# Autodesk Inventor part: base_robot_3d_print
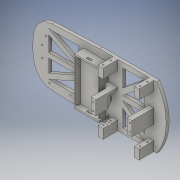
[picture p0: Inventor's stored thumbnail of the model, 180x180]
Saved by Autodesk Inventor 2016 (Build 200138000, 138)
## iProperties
Created: 2016-07
Part Number: base_robot_3d_print
Material: Generic
Document SubType Name: Modeling
Designer: jose
Density: 1 g/cm^3
Appearance: Default
Author: jose
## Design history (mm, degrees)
sketch "Sketch1"
  geometry: C1 r 88.9 at (0, 0); 1 further point
  constraints: 1 centre point, 1 coincident
  dimensions: "d0" = 177.8 diameter of C1
extrude "Extrusion1" new body sketch "Sketch1" distance "d1" = 4.0894; taper "d2" = 0 deg
sketch "Sketch2"
  geometry: L1 (0, 88.9)-(76.2, 88.9); L2 (76.2, 88.9)-(76.2, -88.9); L3 (76.2, -88.9)-(0, -88.9); L4 (0, -88.9)-(0, 88.9); C1 r 88.9 at (0, 0) reference; A1 r 88.9 centre (0, 0) between (0, -88.9) and (0, 88.9); 2 further points
  constraints: 8 end point, 3 horizontal, 2 parallel, 2 point on circle, 1 centre point, 1 coincident, 1 perpendicular, 1 vertical alignment, 1 other
  dimensions: "d6" = 76.2 distance from line of point (0, 0) L2
extrude "Extrusion2" join sketch "Sketch2" stored distance "d4" = 3.175; taper "d5" = 0 deg
fillet "Fillet1" dims "d7" = 12.7
workplane "Work Plane1"
sketch "Sketch4"
  geometry: L1 (68.9, 8.25)-(68.9, -8.25) reference; L2 (-76.2, -7.461)-(-76.2, 7.461); L3 (0, 0)-(-20.048, 0) reference; C1 r 0.953 at (-76.2, 7.461); C2 r 0.953 at (-76.2, -7.461); C3 r 1.6 at (-23.495, 19.05); C4 r 2 at (73.4, -5); C5 r 2 at (24.395, 5); C6 r 0.953 at (-66.675, -31.75); C7 r 0.953 at (-38.735, -31.75); C8 r 0.953 at (-71.755, 20.32); C9 r 0.953 at (-23.495, 19.05); C10 r 0.635 at (24.395, -5); C11 r 0.635 at (24.395, 5); C12 r 0.635 at (73.4, -5); C13 r 0.635 at (73.4, 5); C14 r 11.062 at (-76.2, 0); C15 r 128.001 at (0, 0); A1 r 2 centre (73.4, 5) between (75, 6.2) and (75, 3.8) reference; A2 r 2 centre (73.4, -5) between (75, -3.8) and (75, -6.2) reference; A3 r 2 centre (24.395, -5) between (22.795, -6.2) and (22.795, -3.8) reference; A4 r 2 centre (24.395, 5) between (22.795, 3.8) and (22.795, 6.2) reference; A5 r 2 centre (66.9, -8.25) between (66.9, -10.25) and (68.9, -8.25) reference; 3 further points
  constraints: 16 centre point, 10 coincident, 6 end point, 5 equal radius, 2 horizontal, 2 point on circle, 2 vertical, 1 midpoint, 12 other
  dimensions: "d37" = 1.905 diameter of C8; "d39" = 1.27 diameter of C10; "d40" = 1.27 diameter of C11; "d41" = 1.27 diameter of C12; "d42" = 1.27 diameter of C13; "d132" = 27.94 distance of C7.centre C6.centre; "d133" = 52.07 vertical distance of C8.centre C6.centre; "d134" = 50.8 vertical distance of C3.centre C7.centre; "d135" = 48.26 horizontal distance of C8.centre C3.centre; "d136" = 15.24 horizontal distance of C7.centre C3.centre; "d137" = 43.18 horizontal distance of C6.centre C3.centre; "d138" = 23.495 horizontal distance of point (0, 0) C3.centre; "d139" = 19.05 vertical distance of point (0, 0) C3.centre; "d236" = 14.9225 distance of L2.end L2.start; "d237" = 76.2 distance from line of point (0, 0) L2; "d238" = 22.1234 diameter of C14
extrude "Extrusion4" cut sketch "Sketch4" stored distance "d14" = 25.4; taper "d15" = 0 deg
sketch "Sketch6"
  geometry: L1 (76.2, -76.2)-(76.2, 76.2) reference; L2 (76.2, 41.2)-(0, 41.2); L3 (0, 41.2)-(0, 88.9); L4 (0, 88.9)-(76.2, 88.9); L5 (76.2, 88.9)-(76.2, 41.2); L6 (0, 41.2)-(54.912, 41.2) reference; L7 (0, 41.2)-(54.912, 41.2) reference; A1 r 88.9 centre (0, 0) between (0, 88.9) and (0, -88.9) reference; 1 further point
  constraints: 8 end point, 2 parallel, 1 horizontal, 1 perpendicular, 1 point on line
  dimensions: "d16" = 0 distance between parallel lines of L6 L2
extrude "Extrusion5" cut sketch "Sketch6" stored distance "d17" = 25.4; taper "d18" = 0 deg
mirror "Mirror2"
sketch "Sketch11"
  geometry: L1 (72.705, -41.2)-(66.218, -41.2); L2 (66.218, 41.2)-(72.705, 41.2); L3 (64.953, 47.485)-(71.705, 47.485) reference; L4 (71.705, -47.42)-(64.953, -47.42) reference; L5 (19.1, -41.2)-(25.852, -41.2); L6 (25.852, 47.485)-(19.1, 47.485) reference; L7 (24.587, -41.2)-(18.1, -41.2); L8 (18.1, 41.2)-(24.587, 41.2); L9 (25.4, -18.92)-(25.4, -47.12) reference; L10 (18.1, -41.2)-(18.1, -28.5); L11 (18.1, 28.5)-(18.1, 41.2); L12 (24.587, 41.2)-(24.587, 28.5); L13 (24.587, -28.5)-(24.587, -41.2); L14 (66.218, -41.2)-(66.218, -28.5); L15 (66.218, 28.5)-(66.218, 41.2); L16 (72.705, 41.2)-(72.705, 28.5); L17 (72.705, -28.5)-(72.705, -41.2); L18 (18.1, -28.5)-(24.587, -28.5); L19 (66.218, -28.5)-(72.705, -28.5); L20 (18.1, 28.5)-(24.587, 28.5); L21 (66.218, 28.5)-(72.705, 28.5); L22 (65.405, -47.12)-(65.405, -18.92) reference; L23 (72.705, -50.12)-(72.705, -47.42) reference; L24 (18.1, -50.12)-(18.1, -47.42) reference; L25 (18.1, -9.375)-(24.587, -9.375); L26 (24.587, -9.375)-(24.587, 9.375); L27 (24.587, 9.375)-(18.1, 9.375); L28 (18.1, 9.375)-(18.1, -9.375); L29 (66.218, -9.375)-(72.705, -9.375); L30 (72.705, -9.375)-(72.705, 9.375); L31 (72.705, 9.375)-(66.218, 9.375); L32 (66.218, 9.375)-(66.218, -9.375); L33 (19.209, -9.911)-(25.96, -9.821) reference; L34 (25.71, 8.928)-(18.959, 8.838) reference; L35 (0, 0)-(-84.571, 0); L36 (0, 41.2)-(-80.571, 37.571); L37 (0, -41.2)-(-80.571, -37.571); L38 (-80.571, 37.571)-(-74.816, 34.887); L39 (-74.816, -34.887)-(-80.571, -37.571); L40 (0, 41.2)-(0, 88.9) reference; A1 r 88.9 centre (0, 0) between (0, 88.9) and (0, -88.9) reference; A2 r 82.55 centre (0, 0) between (-74.816, 34.887) and (-74.816, -34.887); A3 r 88.9 centre (0, 0) between (0, 88.9) and (0, -88.9) reference; A4 r 88.9 centre (0, 0) between (-80.571, 37.571) and (-80.571, -37.571); 5 further points; 2 other entities
  constraints: 61 end point, 12 collinear, 11 horizontal, 11 parallel, 6 point on circle, 4 perpendicular, 3 point on line, 2 centre point, 2 line through centre, 1 symmetric about line, 4 other
  dimensions: "d55" = 12.7 distance between parallel lines of L8 L20; "d56" = 12.7 distance of L15.start L2.start; "d57" = 12.7 distance of L1.end L14.end; "d58" = 12.7 distance of L10.end L7.end; "d59" = 0.8128 distance between parallel lines of L22 L14; "d60" = 0.8128 distance between parallel lines of L13 L9; "d67" = 6.35 radial gap between concentric circles of A1 A2; "d72" = 25 deg angle of L35 L38
extrude "Extrusion12" join sketch "Sketch11" distance "d70" = 19.8628; taper "d71" = 0 deg
sketch "Sketch13"
  geometry: L1 (-6.487, 0)-(-48.118, 0) reference; L2 (-2.8, -5.922)-(-2.8, -15.922); L3 (-51.805, -15.922)-(-51.805, -5.922); L4 (-2.8, -5.922)-(-51.805, -5.922); L5 (0, 0)-(0, -19.863) reference; C1 r 0.953 at (-2.8, -15.922); C2 r 0.953 at (-2.8, -5.922); C3 r 0.953 at (-51.805, -5.922); C4 r 0.953 at (-51.805, -15.922); 1 further point
  constraints: 6 end point, 4 centre point, 3 equal radius, 2 vertical, 1 horizontal
  dimensions: "d73" = 1.905 diameter of C1; "d213" = 10 distance of L3.start L3.end; "d216" = 49.005 distance between parallel lines of L3 L2; "d217" = 10 distance of L2.start L2.end; "d218" = 2.8 distance between parallel lines of L5 L2; "d219" = 5.922 distance between parallel lines of L1 L4
extrude "Extrusion13" cut sketch "Sketch13" distance "d77" = 12.7; taper "d78" = 0 deg
sketch "Sketch15"
  geometry: C1 r 0.953 at (-3.687, 15.922) reference; C2 r 0.953 at (-3.687, 5.922) reference; C3 r 0.953 at (45.318, 15.922) reference; C4 r 0.953 at (45.318, 5.922) reference; 1 further point
extrude "Extrusion14" cut sketch "Sketch15" distance "d83" = 12.7; taper "d84" = 0 deg
sketch "Sketch16"
  geometry: C1 r 0.953 at (69.951, -4.857); C2 r 0.953 at (69.818, 5.142); C3 r 0.953 at (20.951, -5.512); C4 r 0.953 at (20.817, 4.487); A1 r 2 centre (69.951, -4.857) between (71.535, -3.636) and (71.567, -6.036) reference; A2 r 2 centre (69.818, 5.142) between (71.401, 6.363) and (71.433, 3.963) reference; A3 r 2 centre (20.951, -5.512) between (19.367, -6.733) and (19.335, -4.334) reference; A4 r 2 centre (20.817, 4.487) between (19.233, 3.266) and (19.201, 5.665) reference; 1 further point
  constraints: 4 centre point, 4 coincident, 3 equal radius
  dimensions: "d119" = 1.905 diameter of C3
extrude "Extrusion15" cut sketch "Sketch16" distance "d89" = 6.35; taper "d90" = 0 deg
sketch "Sketch17"
  geometry: L1 (66.218, -9.375)-(72.705, -9.375) reference; L2 (72.705, -9.375)-(72.705, 9.375) reference; L3 (72.705, 9.375)-(66.218, 9.375) reference; L4 (66.218, 9.375)-(66.218, -9.375) reference; L5 (18.1, -9.375)-(24.587, -9.375) reference; L6 (24.587, -9.375)-(24.587, 9.375) reference; L7 (24.587, 9.375)-(18.1, 9.375) reference; L8 (18.1, 9.375)-(18.1, -9.375) reference; C1 r 0.953 at (69.951, -4.857) reference; C2 r 0.953 at (69.818, 5.142) reference; C3 r 0.953 at (20.951, -5.512) reference; C4 r 0.953 at (20.817, 4.487) reference; 1 further point
extrude "Extrusion16" join sketch "Sketch17" distance "d91" = 9.525; taper "d92" = 0 deg
sketch "Sketch18"
  geometry: L1 (0, -88.9)-(0, -41.2) reference; L2 (0, -41.2)-(-80.571, -37.571) reference; L3 (0, 41.2)-(-80.571, 37.571) reference; L4 (0, 41.2)-(0, 88.9) reference; A1 r 88.9 centre (0, 0) between (0, 88.9) and (0, -88.9) reference; 1 further point
extrude "Extrusion17" cut sketch "Sketch18" stored distance "d93" = 12.7; taper "d94" = 0 deg
fillet "Fillet5" dims "d95" = 25.4
sketch "Sketch19"
  geometry: L1 (-54.978, 15.24)-(5.4, 15.24); L2 (5.4, 15.24)-(5.4, 0); L3 (5.4, 0)-(-54.978, 0) reference; L4 (-54.978, 0)-(-54.978, 15.24); L5 (30.937, 31.04)-(59.868, 31.04); L6 (59.868, 31.04)-(59.868, -31.04); L7 (59.868, -31.04)-(30.937, -31.04); L8 (30.937, -31.04)-(30.937, 31.04); L9 (66.218, -41.2)-(72.705, -41.2) reference; L10 (66.218, -28.5)-(66.218, -41.2) reference; L11 (24.587, -41.2)-(24.587, -28.5) reference; L12 (18.1, 9.375)-(18.1, -9.375) reference; L13 (24.587, -9.375)-(24.587, 9.375) reference; L14 (66.218, 41.2)-(66.218, 28.5) reference; L15 (24.587, 41.2)-(18.1, 41.2) reference; L16 (-54.978, 0)-(-54.978, -15.24); L17 (-54.978, -15.24)-(5.4, -15.24); L18 (5.4, -15.24)-(5.4, 0); L19 (5.4, 45.004)-(-54.978, 32.768); L20 (0, 41.2)-(-63.303, 38.349) reference; L21 (-54.978, 32.768)-(-54.978, 25.4); L22 (-54.978, 25.4)-(5.4, 25.4); L23 (5.4, 45.004)-(5.4, 25.4); L24 (-54.978, -25.4)-(5.4, -25.4); L25 (-54.978, -32.768)-(-54.978, -25.4); L26 (5.4, -45.004)-(5.4, -25.4); L27 (59.868, 31.04)-(30.937, 2.109); L28 (59.868, 22.06)-(30.937, -6.871); L29 (30.937, 3.175)-(59.868, 3.175); L30 (59.868, 3.175)-(59.868, -3.175); L31 (59.868, -3.175)-(30.937, -3.175); L32 (30.937, -3.175)-(30.937, 3.175); L33 (59.868, -22.06)-(30.937, 6.871); L34 (59.868, -31.04)-(30.937, -2.109); L35 (-45.72, -25.4)-(-45.72, -34.644); L36 (-35.56, -25.4)-(-35.56, -36.703); L37 (-71.581, -29.403)-(-54.978, -32.768); L38 (5.4, -45.004)-(-64.902, -30.756); L39 (-65.724, -31.803)-(-67.525, -31.32); L40 (66.218, 41.2)-(24.587, 41.2) reference; C1 r 0.953 at (-76.2, -7.461) reference; C2 r 0.953 at (-73.66, 20.32) reference; C3 r 0.953 at (-40.64, -31.75) reference; A1 r 3.81 centre (-68.58, -31.75) between (-64.902, -30.756) and (-71.581, -29.403); 2 further points
  constraints: 62 end point, 12 point on line, 9 parallel, 6 symmetric about line, 4 horizontal, 4 perpendicular, 3 collinear, 3 vertical, 2 point on circle, 1 centre point, 1 coincident, 5 other
  dimensions: "d96" = 10.16 dimension on C1.centre L4; "d97" = 12.7 distance between parallel lines of L12 L2; "d98" = 6.35 distance between parallel lines of L13 L8; "d99" = 6.35 distance between parallel lines of L14 L6; "d100" = 5.08 distance from line of C2.centre L1; "d101" = 6.35 distance between parallel lines of L27 L28; "d102" = 3.175 distance between parallel lines of L3 L29; "d103" = 3.175 distance between parallel lines of L3 L31; "d105" = 6.35 distance between parallel lines of L33 L34; "d124" = 3.81 radius of A1; "d125" = 10.16 distance between parallel lines of L17 L24; "d127" = 10.16 distance between parallel lines of L36 L35; "d128" = 5.08 distance from line of C3.centre L36; "d129" = 19.60437 distance of L26.start L24.end; "d130" = 45 deg angle of L27 L5; "d131" = 10.16 distance between parallel lines of L40 L5
extrude "Extrusion19" cut sketch "Sketch19" stored distance "d108" = 0; taper "d109" = 0 deg
sketch "Sketch20"
  geometry: L1 (18.1, 9.375)-(24.587, 9.375) reference; L2 (24.587, -9.375)-(18.1, -9.375) reference; L3 (18.1, 9.375)-(24.587, 9.375); L4 (24.587, 9.375)-(24.587, -9.375); L5 (24.587, -9.375)-(18.1, -9.375); L6 (18.1, -9.375)-(18.1, 9.375); 1 further point
  constraints: 8 end point, 2 parallel, 1 horizontal, 1 perpendicular
chamfer "Chamfer1" distance "d110" = 10.16; stored, may be unused: second distance "d111" = 3.175, angle "d112" = 30 deg
sketch "Sketch21"
  geometry: L1 (6.487, -29.388)-(6.487, 0) reference; L2 (6.487, -18.69)-(0.311, -29.388); L3 (-5.866, -29.388)-(0, -19.228) reference; L4 (6.487, -15.54)-(-1.508, -29.388); 2 further points; 1 other entity
  constraints: 4 end point, 2 point on line, 1 parallel, 3 other
  dimensions: "d200" = 1.5748 distance between parallel lines of L4 L2
extrude "Extrusion20" cut sketch "Sketch21" distance "d113" = 15.24; taper "d114" = 0 deg
sketch "Sketch22"
  geometry: L1 (0, 18.75)-(0, 0) reference; L2 (0, 3.505)-(-3.81, 3.505); L3 (-3.81, 3.505)-(-3.81, 15.24); L4 (-3.81, 15.24)-(0, 15.24); L5 (0, 15.24)-(0, 3.505); L6 (-29.388, 0)-(-29.388, 18.75) reference; L7 (-29.388, 9.375)-(0, 9.375); L8 (-13.848, 15.24)-(0, 15.24) reference; L9 (0, 18.75)-(-29.388, 18.75) reference; 2 further points
  constraints: 10 end point, 2 parallel, 2 perpendicular, 2 point on line, 1 collinear, 1 horizontal, 1 midpoint
  dimensions: "d116" = 3.81 distance between parallel lines of L1 L3; "d120" = 3.51 distance between parallel lines of L4 L9 (derived); "d121" = 3.5052 distance from line of L1.end L2
extrude "Extrusion21" cut sketch "Sketch22" stored distance "d117" = 15.24; taper "d118" = 0 deg
sketch "Sketch36"
  geometry: L1 (12.234, -31.75)-(-20.786, -31.75); L2 (-20.786, -31.75)-(-20.786, 31.75); L3 (-20.786, 31.75)-(12.234, 31.75); L4 (12.234, 31.75)-(12.234, -31.75); L5 (12.234, -5.87)-(12.234, -9.375) reference; L6 (0, 0)-(-41.856, 0)
  constraints: 10 end point, 2 horizontal, 2 parallel, 1 collinear, 1 perpendicular, 1 other
  dimensions: "d175" = 63.5 distance between parallel lines of L3 L1; "d176" = 33.02 distance of L1.start L1.end
extrude "Extrusion29" join sketch "Sketch36" distance "d177" = 12.7; taper "d178" = 0 deg
sketch "Sketch37"
  geometry: L1 (-18.817, 23.749)-(-18.817, -23.749) reference; L2 (-12.975, -29.591)-(4.424, -29.591) reference; L3 (10.266, 23.749)-(10.266, -23.749) reference; L4 (-12.975, 29.591)-(4.424, 29.591) reference; L5 (10.964, -29.718)-(-19.516, -29.718); L6 (-19.516, -29.718)-(-19.516, 29.718); L7 (-19.516, 29.718)-(10.964, 29.718); L8 (10.964, 29.718)-(10.964, -29.718); L9 (11.015, -29.769)-(-19.567, -29.769); L10 (-19.567, -29.769)-(-19.567, 29.769); L11 (-19.567, 29.769)-(11.015, 29.769); L12 (11.015, 29.769)-(11.015, -29.769); L13 (10.266, 0)-(17.737, 0); L14 (-4.276, 29.591)-(-4.276, 42.475); C1 r 2.921 at (-12.251, -21.933) reference; C2 r 3.683 at (-12.251, -7.366) reference; A1 r 5.842 centre (-12.975, 23.749) between (-12.975, 29.591) and (-18.817, 23.749) reference; A2 r 5.842 centre (-12.975, -23.749) between (-18.817, -23.749) and (-12.975, -29.591) reference; A3 r 5.842 centre (4.424, -23.749) between (4.424, -29.591) and (10.266, -23.749) reference; A4 r 5.842 centre (4.424, 23.749) between (10.266, 23.749) and (4.424, 29.591) reference; 1 further point
  constraints: 20 end point, 4 parallel, 2 horizontal, 2 midpoint, 2 perpendicular, 1 vertical, 5 other
  dimensions: "d179" = 0.0508 distance between parallel lines of L8 L12; "d180" = 59.436 distance between parallel lines of L5 L7; "d181" = 30.48 distance between parallel lines of L6 L8
extrude "Extrusion30" cut sketch "Sketch37" distance "d182" = 12.7; taper "d183" = 0 deg
sketch "Sketch39"
  geometry: L1 (1.219, -12.7)-(31.801, -12.7) reference; L2 (16.51, -12.7)-(16.51, 5.119); L3 (19.685, -10.16)-(13.335, -10.16); L4 (13.335, -10.16)-(13.335, -7.62); L5 (13.335, -7.62)-(19.685, -7.62); L6 (19.685, -7.62)-(19.685, -10.16); 1 further point
  constraints: 10 end point, 2 parallel, 1 horizontal, 1 midpoint, 1 perpendicular, 1 vertical, 1 other
  dimensions: "d185" = 6.35 distance of L4.end L5.end; "d186" = 2.54 distance between parallel lines of L3 L5; "d187" = 2.54 distance between parallel lines of L3 L1
extrude "Extrusion31" cut sketch "Sketch39" stored distance "d188" = 12.7; taper "d189" = 0 deg
sketch "Sketch40"
  geometry: L1 (76.2, -45.791)-(91.44, -45.791); L2 (91.44, -45.791)-(91.44, 45.791); L3 (91.44, 45.791)-(76.2, 45.791); L4 (76.2, 45.791)-(76.2, 41.2); L5 (76.2, -41.2)-(76.2, -45.791); L6 (72.705, -41.2)-(76.2, -41.2) reference; L7 (88.9, 0)-(97.626, 0); A1 r 73.178 centre (15.722, 0) between (76.2, -41.2) and (76.2, 41.2); A2 r 88.9 centre (0, 0) between (76.2, -45.791) and (76.2, 45.791) reference; 2 further points
  constraints: 12 end point, 5 point on circle, 3 parallel, 2 horizontal, 2 point on line, 1 centre point, 1 perpendicular
  dimensions: "d190" = 2.54 distance edge to line of A1 L2
extrude "Extrusion32" cut sketch "Sketch40" stored distance "d191" = 12.7; taper "d192" = 0 deg
extrude "Extrusion33" cut sketch "Sketch22" stored distance "d193" = 12.7; taper "d194" = 0 deg
sketch "Sketch41"
  geometry: L1 (12.7, 22.324)-(7.315, 22.324); L2 (7.315, 22.324)-(7.315, 37.209); L3 (7.315, 37.209)-(12.7, 37.209); L4 (8.89, 35.634)-(12.7, 35.634) reference; L5 (8.89, 23.899)-(8.89, 35.634) reference; L6 (12.7, 23.899)-(8.89, 23.899) reference; L7 (12.744, 22.324)-(12.744, 23.899); L8 (12.744, 23.899)-(8.89, 23.899); L9 (12.7, 0)-(12.7, 23.899) reference; L10 (12.7, 23.899)-(12.7, 22.324); L11 (8.89, 23.899)-(8.89, 35.634); L12 (8.89, 35.634)-(12.7, 35.634); L13 (12.7, 35.634)-(12.7, 37.209); 1 further point
  constraints: 18 end point, 4 perpendicular, 2 horizontal, 2 vertical, 1 point on line
  dimensions: "d195" = 1.5748 distance between parallel lines of L4 L3; "d196" = 1.5748 distance between parallel lines of L5 L2; "d197" = 1.5748 distance between parallel lines of L6 L1
extrude "Extrusion34" join sketch "Sketch41" stored distance "d198" = 12.7; taper "d199" = 0 deg
sketch "Sketch42"
  geometry: L1 (0, -5.385)-(0, 0) reference; L2 (3.109, 0)-(0, -5.385) reference; L3 (0, 0)-(3.109, 0) reference; 1 further point
extrude "Extrusion35" join sketch "Sketch42" stored distance "d201" = 12.7; taper "d202" = 0 deg
sketch "Sketch43"
  geometry: L1 (0, 0)-(0, 5.385) reference; L2 (0, 0)-(3.109, 0) reference; L3 (0, 5.385)-(3.109, 0) reference; 1 further point
extrude "Extrusion36" join sketch "Sketch43" stored distance "d203" = 12.7; taper "d204" = 0 deg
sketch "Sketch44"
  geometry: L1 (11.015, 29.769)-(11.015, -29.769) reference; L2 (11.015, -29.769)-(-19.623, -29.769); L3 (-19.623, -29.769)-(-19.623, -7.445); L4 (-19.623, -7.445)-(11.015, -7.445); L5 (11.015, -7.445)-(11.015, -29.769); L6 (11.015, 29.769)-(-19.623, 29.769); L7 (-19.623, 29.769)-(-19.623, 7.44); L8 (-19.623, 7.44)-(11.015, 7.44); L9 (11.015, 7.44)-(11.015, 29.769); L10 (-19.567, -7.445)-(11.015, -7.445) reference; L11 (-19.567, 7.44)-(11.015, 7.44) reference; 1 further point
  constraints: 16 end point, 4 parallel, 2 collinear, 2 horizontal, 2 perpendicular
extrude "Extrusion37" join sketch "Sketch44" stored distance "d207" = 12.7; taper "d208" = 0 deg
workaxis "Work Axis1"
workaxis "Work Axis2"
sketch "Sketch45"
  geometry: L1 (-15.922, -16.48)-(-15.922, 98.88) reference; L2 (-5.922, -16.48)-(-5.922, 98.88) reference; L3 (0, 12.7)-(-19.863, 12.7) reference; L4 (-10.918, 12.7)-(-10.918, 0); L5 (0, 0)-(-19.863, 0) reference; L6 (-12.506, 12.7)-(-9.331, 12.7); L7 (-9.331, 12.7)-(-9.331, 11.112); L8 (-9.331, 11.112)-(-12.506, 11.112); L9 (-12.506, 11.112)-(-12.506, 12.7); 1 further point
  constraints: 10 end point, 3 point on line, 2 parallel, 1 horizontal, 1 perpendicular, 1 vertical, 1 other
  dimensions: "d209" = 10 distance between parallel lines of L2 L1 (derived); "d210" = 5.0038 distance between parallel lines of L1 L4; "d211" = 3.175 distance between parallel lines of L7 L9; "d212" = 1.5875 distance of L6.end L7.end
extrude "Extrusion38" cut sketch "Sketch45" stored distance "d220" = 12.7; taper "d221" = 0 deg
fillet "Fillet6" dims "d222" = 1.5875
mirror "Mirror8"
sketch "Sketch47"
  geometry: L1 (12.7, 23.904)-(5.385, 23.904) reference; L2 (12.7, -35.634)-(5.385, -35.634) reference; L3 (12.7, 25.885)-(12.7, -37.615) reference; L4 (12.7, -33.369)-(9.144, -33.369); L5 (12.7, 21.484)-(9.144, 21.484); L6 (9.144, -35.634)-(9.144, -33.369); L7 (9.144, 21.484)-(9.144, 23.904); 2 further points
  constraints: 8 end point, 4 point on line, 2 horizontal, 2 perpendicular
extrude "Extrusion39" cut sketch "Sketch47" stored distance "d224" = 12.7; taper "d225" = 0 deg
sketch "Sketch48"
  geometry: L1 (59.868, -34.85)-(30.937, -34.85); L2 (30.937, -34.85)-(30.937, 34.85); L3 (30.937, 34.85)-(59.868, 34.85); L4 (59.868, 34.85)-(59.868, -34.85); L5 (24.587, -28.5)-(24.587, -41.2) reference; L6 (66.218, -28.5)-(66.218, -41.2) reference; L7 (0, 41.2)-(76.2, 41.2) reference; L8 (24.587, -41.2)-(66.218, -41.2) reference; L9 (66.218, 9.375)-(66.218, -9.375) reference; L10 (-20.786, 5.865)-(-20.786, -5.87) reference; L11 (59.868, -3.175)-(30.937, -3.175); L12 (30.937, 3.175)-(59.868, 3.175); L13 (80.918, 0)-(-41.838, 0) reference; L14 (30.937, -11.355)-(59.868, -34.85); L15 (59.868, -26.67)-(30.937, -3.175); L16 (30.937, 3.175)-(59.868, 26.67); L17 (59.868, 34.85)-(30.937, 11.355); 1 further point
  constraints: 22 end point, 8 point on line, 4 parallel, 3 horizontal, 3 perpendicular, 1 other
  dimensions: "d226" = 6.35 distance between parallel lines of L5 L2; "d227" = 6.35 distance between parallel lines of L6 L4; "d228" = 6.35 distance between parallel lines of L7 L3; "d229" = 6.35 distance between parallel lines of L8 L1; "d231" = 6.35 distance between parallel lines of L11 L12; "d232" = 6.35 distance between parallel lines of L14 L15; "d233" = 6.35 distance between parallel lines of L17 L16
extrude "Extrusion40" cut sketch "Sketch48" stored distance "d234" = 12.7; taper "d235" = 0 deg
sketch "Sketch23"
  geometry: L1 (-9.388, -36.756)-(-9.388, 37.232); L2 (-9.388, 37.232)-(-2.495, 37.232); L3 (-2.495, 37.232)-(-2.495, -36.756); L4 (-2.495, -36.756)-(-9.388, -36.756); 1 further point
  constraints: 2 other
sketch "Sketch49"
  geometry: L1 (-27.623, 30.798)-(-67.627, 30.798); L2 (-67.627, 30.798)-(-67.627, -27.622); L3 (-67.627, -27.622)-(-27.622, -27.622); L4 (-27.622, -27.622)-(-27.623, 30.798); L5 (-20.786, 5.865)-(-20.786, -5.87) reference; L6 (-20.786, -0.002)-(-84.618, -0.002) reference; L7 (-27.622, -3.175)-(-67.627, -3.175); L8 (30.937, -3.175)-(59.868, -3.175) reference; L9 (-27.622, 3.175)-(-67.627, 3.175); L10 (59.868, 3.175)-(30.937, 3.175) reference; L11 (-67.627, -27.622)-(-27.622, -10.107); L12 (-67.627, 30.798)-(-27.622, 10.309); L13 (-27.622, 3.175)-(-67.627, 23.663); L14 (-27.622, -3.175)-(-67.627, -20.691); C1 r 0.953 at (-38.735, -31.75) reference; C2 r 0.953 at (-71.755, 20.32) reference; C3 r 0.953 at (-23.495, 19.05) reference; 1 further point
  constraints: 22 end point, 8 point on line, 4 parallel, 3 horizontal, 3 perpendicular, 2 collinear, 1 midpoint
  dimensions: "d239" = 3.175 distance edge to line of C1 L3; "d240" = 3.175 distance edge to line of C2 L2; "d241" = 3.175 distance edge to line of C3 L4; "d242" = 58.42 distance between parallel lines of L3 L1; "d243" = 6.35 distance between parallel lines of L11 L14; "d244" = 6.35 distance between parallel lines of L12 L13
extrude "Extrusion41" cut sketch "Sketch49" stored distance "d245" = 25.4; taper "d246" = 0 deg
emboss "Emboss1" sketch "Sketch23" dims "d247" = 0.55, "d248" = 0
sketch "Sketch50"
  geometry: L1 (0, -37.615)-(0, -11.735) reference; L2 (0, -34.365)-(3.81, -34.365); L3 (3.81, -34.365)-(3.81, -22.63); L4 (3.81, -22.63)-(0, -22.63); L5 (0, -22.63)-(0, -34.365); L6 (0, 0)-(0, 25.885) reference; L7 (0, 22.635)-(3.81, 22.635); L8 (3.81, 22.635)-(3.81, 10.9); L9 (3.81, 10.9)-(0, 10.9); L10 (0, 10.9)-(0, 22.635); L11 (3.81, 0)-(3.81, -11.735) reference; L12 (0, -34.365)-(9.331, -34.365) reference; L13 (0, 22.635)-(9.331, 22.635) reference; 1 further point
  constraints: 16 end point, 5 collinear, 4 parallel, 3 point on line, 2 horizontal, 2 perpendicular
extrude "Extrusion42" cut sketch "Sketch50" stored distance "d249" = 25.4; taper "d250" = 0 deg
body "Solid1"
node "Projected Loop1"
node "Reference11"
node "Reference12"
node "Reference13"
node "Reference14"
node "Reference15"
node "Reference16"
node "Reference50"
node "Reference51"
node "Reference53"
node "Reference54"
node "Reference55"
node "Reference56"
node "Reference57"
node "Reference58"
node "Reference59"
node "Reference68"
node "Reference69"
node "Reference70"
node "Reference71"
node "Projected Loop2"
node "Projected Loop3"
node "Reference76"
node "Projected Loop6"
node "Projected Loop7"
other parameters: "d51" = 10.16, "d52" = 10.16, "d53" = 0.8128, "d54" = 12.7, "d223" = 3.556
